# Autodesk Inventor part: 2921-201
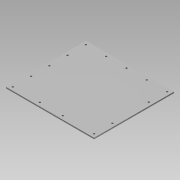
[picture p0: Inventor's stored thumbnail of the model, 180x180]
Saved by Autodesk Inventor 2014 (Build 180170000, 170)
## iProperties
Company: NHTSA/VRTC
Created: 2012-08
Part Number: 2921-201
Material: Steel, Mild
Document SubType Name: Modeling
Designer: Mike Vanvoorhis
Density: 7.86 g/cm^3
Mass: 28050.4 g
Surface Area: 7780.01 cm^2
Volume: 3568.75 cm^3
Project: CHILD SIDE IMPACT SLED
Description: IMPACTOR BASE PLATE
Stock Number: PL 9.5 (3/8") x 584.2 (23") x 644.5 (25 3/8")
Appearance: Steel
Author: Dave Walker
Title: Impactor Base Plate
Subject: Child Side Impact Sled
Revision Number: A
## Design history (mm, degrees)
derived "Impactor_Frame_Part 7_MIR.ipt"
  sketch "Sketch1"
    geometry: L1 (0, 0)-(644.525, 0) reference; L2 (644.525, 0)-(644.525, 9.525) reference; L3 (644.525, 9.525)-(0, 9.525) reference; L4 (0, 9.525)-(0, 0) reference
  sketch "Sketch2"
    geometry: L1 (0, 0)-(0, 584.2) reference; L2 (644.525, 0)-(644.525, 584.2) reference; L3 (0, 25.4)-(25.4, 25.4) reference; L4 (25.4, 25.4)-(25.4, 158.75) reference; L5 (25.4, 158.75)-(25.4, 292.1) reference; L6 (25.4, 292.1)-(25.4, 425.45) reference; L7 (25.4, 425.45)-(25.4, 558.8) reference; L8 (25.4, 25.4)-(222.25, 25.4) reference; L9 (644.525, 25.4)-(619.125, 25.4) reference; L10 (619.125, 25.4)-(390.525, 25.4) reference; L11 (619.125, 25.4)-(619.125, 158.75) reference; L12 (619.125, 158.75)-(619.125, 292.1) reference; L13 (619.125, 292.1)-(619.125, 425.45) reference; L14 (619.125, 425.45)-(619.125, 558.8) reference; L15 (25.4, 558.8)-(173.831, 558.8) reference; L16 (173.831, 558.8)-(322.262, 558.8) reference; L17 (322.262, 558.8)-(470.694, 558.8) reference; C1 r 6.747 at (25.4, 25.4) reference; C2 r 6.747 at (25.4, 158.75) reference; C3 r 6.747 at (25.4, 292.1) reference; C4 r 6.747 at (25.4, 425.45) reference; C5 r 6.747 at (25.4, 558.8) reference; C6 r 6.747 at (619.125, 25.4) reference; C7 r 6.747 at (390.525, 25.4) reference; C8 r 6.747 at (222.25, 25.4) reference; C9 r 6.747 at (619.125, 158.75) reference; C10 r 6.747 at (619.125, 558.8) reference; C11 r 6.747 at (173.831, 558.8) reference; C12 r 6.747 at (322.262, 558.8) reference; C13 r 6.747 at (470.694, 558.8) reference
sketch "Sketch3"
  geometry: C1 r 6.747 at (619.125, 558.8) reference; 1 further point
  constraints: 1 vertical alignment
  dimensions: "d1" = 133.35 distance of point (619.125, 425.45) C1.centre
hole "Hole1" sketch "Sketch3" at (619.125, 425.45) diameter "d2" = 13.4874; stored, may be unused: countersink angle "d6" = 82 deg, drill point angle "d8" = 118 deg; dims "d3" = 19.05, "d4" = 9.525, "d5" = 6.35, "d7" = 25.4
feature "Solid1::Impactor_Frame_Part 7_MIR.ipt" dims "d0" = 10
tag "TaggingFeature1"
body "Solid1"
